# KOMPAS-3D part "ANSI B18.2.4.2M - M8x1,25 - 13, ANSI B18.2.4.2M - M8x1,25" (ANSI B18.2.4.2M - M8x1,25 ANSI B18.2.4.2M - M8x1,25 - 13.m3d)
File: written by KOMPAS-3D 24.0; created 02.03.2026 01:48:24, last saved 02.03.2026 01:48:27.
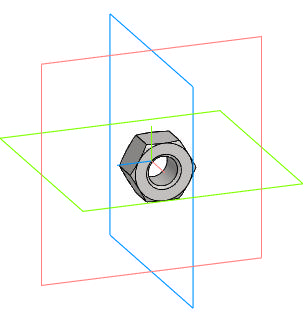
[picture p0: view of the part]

Document properties: Автор: R2D2; Полное имя файла: E:\Работа\Зайцев\GVWR3131M-2W-F-S Задвижка клиновая с выдвижным штоком DN.ru Ду50-200 Ру63\DN150\исходные материалы\ANSI B18.2.4.2M - M8x1,25 ANSI B18.2.4.2M - M8x1,25 - 13.m3d

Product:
- Body: Solid1  | qty 1
    Масса: 0.006562
- Body: Solid1  | qty 1
    Масса: 0.006562
- Part/product: ANSI B18.2.4.2M - M8x1,25 - 13  | designation ANSI B18.2.4.2M - M8x1,25
    Масса: 0.006562
    Комментарий: Типы метрических   шестигранных гаек   2
    additional columns: Сталь, мягкая
- Part/product: ANSI B18.2.4.2M - M8x1,25 - 13  | designation ANSI B18.2.4.2M - M8x1,25-01
    Масса: 0.006562
    Комментарий: Типы метрических   шестигранных гаек   2
    additional columns: Сталь, мягкая

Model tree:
1. Solid1  (labels: Solid1)

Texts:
  ANSI B18.2.4.2M - M8x1,25
  ANSI B18.2.4.2M - M8x1,25-01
